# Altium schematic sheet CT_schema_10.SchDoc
size 274 x 160 mm
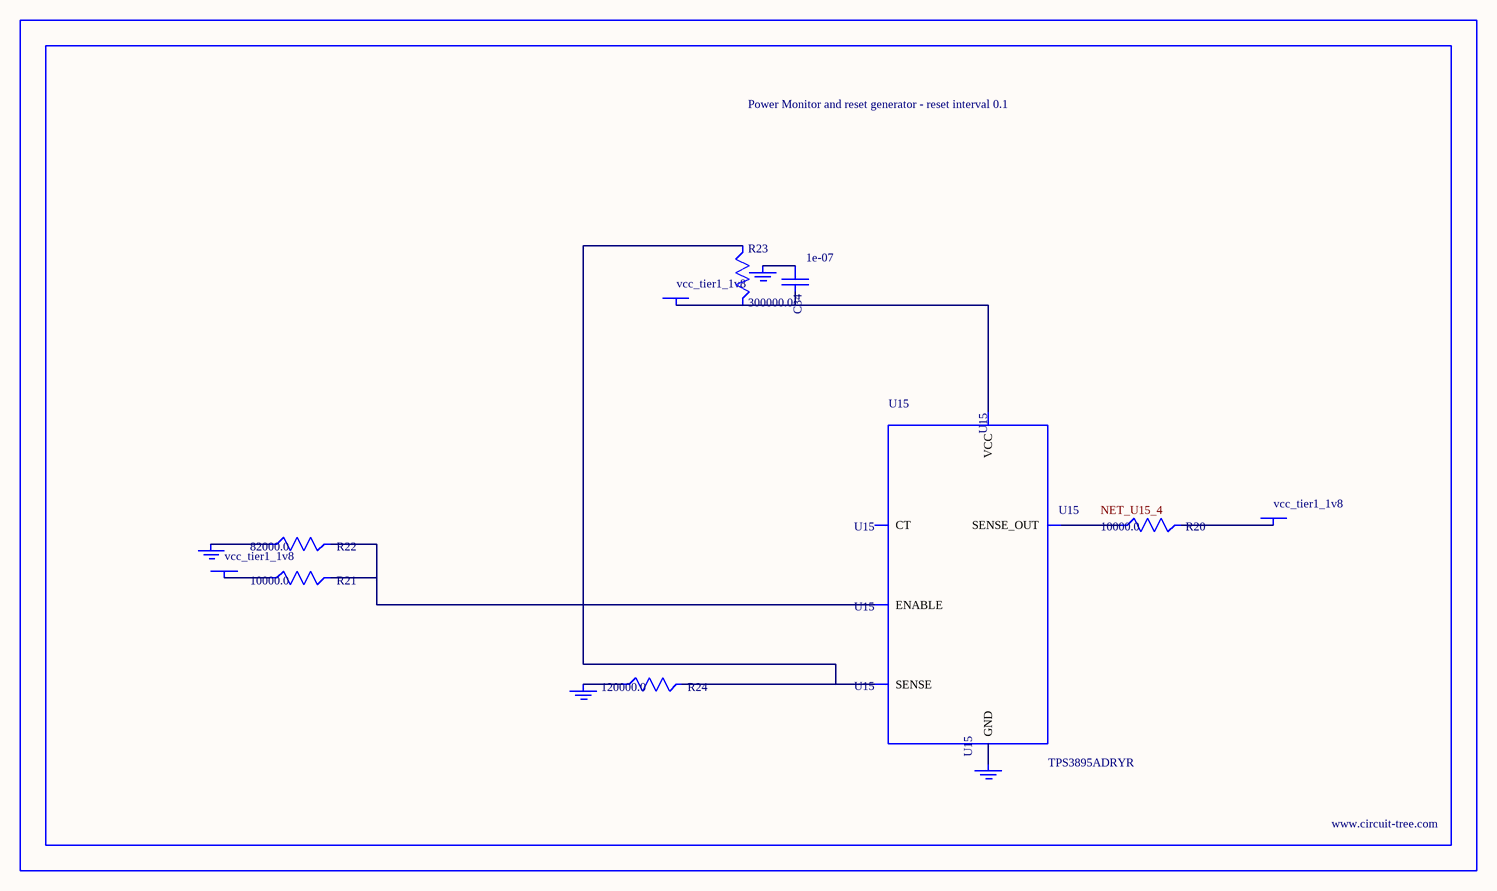
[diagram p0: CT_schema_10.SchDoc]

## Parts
BORDER9  (no value)
C34  1e-07  [C0402]
GND_INSTANCE_9_0  (no value)
GND_INSTANCE_9_1  (no value)
GND_INSTANCE_9_2  (no value)
GND_INSTANCE_9_3  (no value)
POWER_INSTANCE_9_0  vcc_tier1_1v8
POWER_INSTANCE_9_1  vcc_tier1_1v8
POWER_INSTANCE_9_2  vcc_tier1_1v8
R20  10000.0  [R0603]
R21  10000.0  [R0603]
R22  82000.0  [R0603]
R23  300000.0  [R0603]
R24  120000.0  [R0603]
U15  TPS3895ADRYR  [SON-6]

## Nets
NetC34_1: C34.1 GND_INSTANCE_9_2.0(GND)
NetC34_2: C34.2 POWER_INSTANCE_9_2.0(PWR) R23.2 U15.6(VCC)
NetGND_INSTANCE_9_0_0: GND_INSTANCE_9_0.0(GND) R22.1
NetGND_INSTANCE_9_1_0: GND_INSTANCE_9_1.0(GND) R24.1
NetGND_INSTANCE_9_3_0: GND_INSTANCE_9_3.0(GND) U15.2(GND)
NetPOWER_INSTANCE_9_0_0: POWER_INSTANCE_9_0.0(PWR) R21.1
NetPOWER_INSTANCE_9_1_0: POWER_INSTANCE_9_1.0(PWR) R20.2
NetR20_1: R20.1 U15.4(SENSE_OUT)
NetR21_2: R21.2 R22.2 U15.1(ENABLE)
NetR23_1: R23.1 R24.2 U15.3(SENSE)

Not connected (* = marked no-connect by the designer): U15 5(CT)

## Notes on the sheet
- Labels drawn without touching a wire or pin: NET_U15_4

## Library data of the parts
BORDER9 = BORDER_PAGE9
C34 = C0402C104K3RACTU
GND_INSTANCE_9_0-GND_INSTANCE_9_3 = GND
POWER_INSTANCE_9_0-POWER_INSTANCE_9_2 = PWR
R20 R21 = RC0603JR-0710KL
R22 = RC0603JR-0782KL
R23 = RC0603JR-07300KL
R24 = RC0603JR-07120KL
